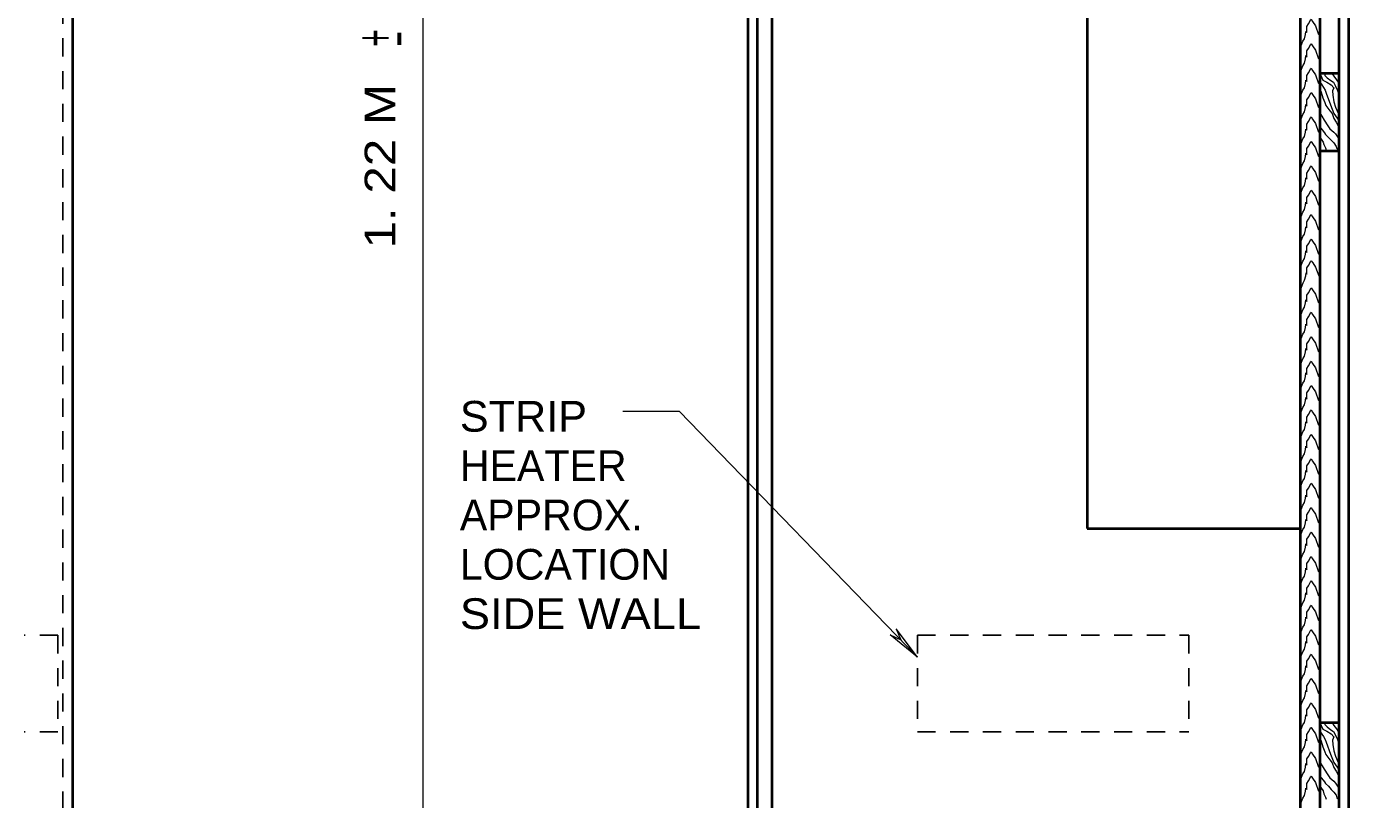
# Model space of a CAD drawing. Extents: x 312583 to 312854, y 144419 to 144597.
# Drawn here: x 312696.89 to 312729.57, y 144529.22 to 144548.34 of the extents above; entities that cross this region are included whole.
import ezdxf
from ezdxf.enums import TextEntityAlignment as Align

# ---------------------------------------------------------------- set-up
doc = ezdxf.new("R2010")
doc.units = 0
doc.header["$LTSCALE"] = 0.3
doc.linetypes.add('SHORT_DASHED', pattern=[2.7, 1.5, -1.2])
doc.layers.add('1', color=7, linetype='Continuous', lineweight=25)
doc.layers.add('2', color=7, linetype='Continuous', lineweight=13)

msp = doc.modelspace()

# ---------------------------------------------------------------- linework, layer by layer
at = {"layer": '1', "lineweight": 40}
for p, q in [((312728.3725, 144566.588), (312728.3725, 144526.338)), ((312728.8555, 144566.542), (312728.8555, 144526.3763)), ((312698.0298, 144565.8673), (312698.0298, 144527.2963)), ((312729.3309, 144565.8673), (312729.3309, 144527.0586)), ((312729.5685, 144565.8673), (312729.5685, 144527.0586)), ((312715.3162, 144564.7863), (312715.3162, 144528.73)), ((312714.9559, 144564.6253), (312714.9559, 144528.8986)), ((312723.1055, 144562.034), (312723.1055, 144535.9213)), ((312728.8555, 144547.1836), (312729.3309, 144547.1836)), ((312728.8555, 144545.267), (312729.3309, 144545.267)), ((312723.1055, 144535.9213), (312728.3725, 144535.9213)), ((312728.8555, 144531.1296), (312729.3309, 144531.1296))]:
    msp.add_line(p, q, dxfattribs=at)
at = {"layer": '1', "linetype": 'SHORT_DASHED'}
for p, q in [((312697.7921, 144565.8673), (312697.7921, 144527.2963)), ((312697.6695, 144533.284), (312696.8338, 144533.284)), ((312697.6695, 144533.284), (312697.6695, 144530.892)), ((312718.9119, 144533.284), (312725.6202, 144533.284)), ((312718.9119, 144533.284), (312718.9119, 144530.892)), ((312725.6202, 144533.284), (312725.6202, 144530.892)), ((312697.6695, 144530.892), (312696.8338, 144530.892)), ((312718.9119, 144530.892), (312725.6202, 144530.892))]:
    msp.add_line(p, q, dxfattribs=at)
at = {"layer": '1', "lineweight": 40}
msp.add_lwpolyline([(312714.7182, 144565.8673), (312714.7182, 144528.2546), (312714.7182, 144527.0586)], dxfattribs=at)
at = {"layer": '2'}
for p, q in [((312706.6978, 144520.8256), (312706.6978, 144566.8256)), ((312711.6283, 144538.8276), (312713.0219, 144538.8276)), ((312718.9119, 144532.7419), (312713.0219, 144538.8276)), ((312718.2351, 144533.2932), (312718.5035, 144533.1681)), ((312718.9119, 144532.7419), (312718.2351, 144533.2932)), ((312718.39, 144533.4416), (312718.5035, 144533.1681)), ((312718.9119, 144532.7419), (312718.39, 144533.4416))]:
    msp.add_line(p, q, dxfattribs=at)
for points in [[(312728.3879, 144547.843), (312728.4415, 144547.9733), (312728.4799, 144548.0346), (312728.5029, 144548.142), (312728.5105, 144548.2186), (312728.5335, 144548.188), (312728.5335, 144548.2723), (312728.5335, 144548.3413), (312728.5795, 144548.4026), (312728.6332, 144548.51), (312728.6409, 144548.5176), (312728.6792, 144548.464), (312728.7482, 144548.3566), (312728.8249, 144548.142)], [(312728.3879, 144547.245), (312728.4415, 144547.3676), (312728.4799, 144547.429), (312728.5029, 144547.5363), (312728.5105, 144547.6206), (312728.5335, 144547.5823), (312728.5335, 144547.6743), (312728.5335, 144547.7356), (312728.5795, 144547.797), (312728.6332, 144547.9043), (312728.6409, 144547.912), (312728.6792, 144547.8583), (312728.7482, 144547.751), (312728.8249, 144547.5363)], [(312728.3879, 144546.6393), (312728.4415, 144546.762), (312728.4799, 144546.8233), (312728.5029, 144546.9306), (312728.5105, 144547.015), (312728.5335, 144546.9766), (312728.5335, 144547.0686), (312728.5335, 144547.13), (312728.5795, 144547.1913), (312728.6332, 144547.2986), (312728.6409, 144547.3063), (312728.6792, 144547.2526), (312728.7482, 144547.1453), (312728.8249, 144546.9306)], [(312728.8555, 144547.1836), (312728.9322, 144547.015), (312729.0319, 144546.9613), (312729.1392, 144546.9), (312729.2005, 144546.8233), (312729.1699, 144546.7466), (312729.1775, 144546.6393), (312729.2005, 144546.4783), (312729.2465, 144546.348), (312729.3079, 144546.1946), (312729.3309, 144546.141)], [(312728.9782, 144547.1836), (312728.9859, 144547.13), (312729.0395, 144547.0686), (312729.1315, 144546.9996), (312729.1929, 144546.9613), (312729.2465, 144546.8616), (312729.2925, 144546.7543), (312729.3309, 144546.6623)], [(312729.1622, 144547.1683), (312729.2005, 144547.107), (312729.2695, 144547.0226), (312729.3155, 144546.9613)], [(312728.3879, 144546.0336), (312728.4415, 144546.164), (312728.4799, 144546.2253), (312728.5029, 144546.3326), (312728.5105, 144546.4093), (312728.5335, 144546.371), (312728.5335, 144546.463), (312728.5335, 144546.5243), (312728.5795, 144546.5856), (312728.6332, 144546.693), (312728.6409, 144546.7083), (312728.6792, 144546.6546), (312728.7482, 144546.5473), (312728.8249, 144546.3326)], [(312728.8632, 144546.9536), (312728.9092, 144546.8923), (312728.9475, 144546.831), (312728.9935, 144546.762), (312729.0165, 144546.693), (312729.1239, 144546.4016), (312729.2082, 144546.187), (312729.3309, 144546.0183)], [(312728.8632, 144546.7773), (312728.8939, 144546.716), (312728.9322, 144546.578), (312728.9782, 144546.4553), (312729.0089, 144546.3863), (312729.1085, 144546.256), (312729.1622, 144546.187), (312729.2082, 144546.0643), (312729.2619, 144545.9723), (312729.3232, 144545.865)], [(312728.3879, 144545.428), (312728.4415, 144545.5583), (312728.4799, 144545.6196), (312728.5029, 144545.727), (312728.5105, 144545.8036), (312728.5335, 144545.773), (312728.5335, 144545.8573), (312728.5335, 144545.9263), (312728.5795, 144545.9876), (312728.6332, 144546.095), (312728.6409, 144546.1026), (312728.6792, 144546.049), (312728.7482, 144545.9416), (312728.8249, 144545.727)], [(312728.8479, 144546.2176), (312728.9629, 144546.026), (312729.0549, 144545.8803), (312729.1085, 144545.8113), (312729.2005, 144545.727), (312729.2465, 144545.681), (312729.3309, 144545.5583)], [(312728.8555, 144545.8573), (312728.9705, 144545.7116), (312729.0012, 144545.6656), (312729.0702, 144545.5966), (312729.1392, 144545.5276), (312729.2005, 144545.4586), (312729.2619, 144545.3743), (312729.2772, 144545.3206), (312729.3232, 144545.2823)], [(312728.3879, 144544.83), (312728.4415, 144544.9526), (312728.4799, 144545.014), (312728.5029, 144545.1213), (312728.5105, 144545.2056), (312728.5335, 144545.1673), (312728.5335, 144545.2593), (312728.5335, 144545.3206), (312728.5795, 144545.382), (312728.6332, 144545.4893), (312728.6409, 144545.497), (312728.6792, 144545.4433), (312728.7482, 144545.336), (312728.8249, 144545.1213)], [(312728.8555, 144545.6043), (312728.9399, 144545.4816), (312728.9552, 144545.4203), (312729.0012, 144545.336), (312729.0165, 144545.2823)], [(312728.3879, 144544.2243), (312728.4415, 144544.347), (312728.4799, 144544.4083), (312728.5029, 144544.5156), (312728.5105, 144544.6), (312728.5335, 144544.5616), (312728.5335, 144544.6536), (312728.5335, 144544.715), (312728.5795, 144544.7763), (312728.6332, 144544.8836), (312728.6409, 144544.8913), (312728.6792, 144544.8376), (312728.7482, 144544.7303), (312728.8249, 144544.5156)], [(312728.3879, 144543.6186), (312728.4415, 144543.749), (312728.4799, 144543.8103), (312728.5029, 144543.9176), (312728.5105, 144543.9943), (312728.5335, 144543.956), (312728.5335, 144544.048), (312728.5335, 144544.1093), (312728.5795, 144544.1706), (312728.6332, 144544.278), (312728.6409, 144544.2933), (312728.6792, 144544.2396), (312728.7482, 144544.1323), (312728.8249, 144543.9176)], [(312728.3879, 144543.013), (312728.4415, 144543.1433), (312728.4799, 144543.2046), (312728.5029, 144543.312), (312728.5105, 144543.3886), (312728.5335, 144543.358), (312728.5335, 144543.4423), (312728.5335, 144543.5113), (312728.5795, 144543.5726), (312728.6332, 144543.68), (312728.6409, 144543.6876), (312728.6792, 144543.634), (312728.7482, 144543.5266), (312728.8249, 144543.312)], [(312728.3879, 144542.415), (312728.4415, 144542.5376), (312728.4799, 144542.599), (312728.5029, 144542.7063), (312728.5105, 144542.7906), (312728.5335, 144542.7523), (312728.5335, 144542.8443), (312728.5335, 144542.9056), (312728.5795, 144542.967), (312728.6332, 144543.0743), (312728.6409, 144543.082), (312728.6792, 144543.0283), (312728.7482, 144542.921), (312728.8249, 144542.7063)], [(312728.3955, 144541.8706), (312728.4492, 144542.001), (312728.4799, 144542.0623), (312728.5105, 144542.1696), (312728.5182, 144542.2463), (312728.5335, 144542.2156), (312728.5335, 144542.3), (312728.5335, 144542.369), (312728.5795, 144542.4303), (312728.6332, 144542.5376), (312728.6409, 144542.5453), (312728.6869, 144542.4916), (312728.7482, 144542.3843), (312728.8325, 144542.1696)], [(312728.3879, 144541.2036), (312728.4415, 144541.334), (312728.4799, 144541.3953), (312728.5029, 144541.5026), (312728.5105, 144541.5793), (312728.5335, 144541.541), (312728.5335, 144541.633), (312728.5335, 144541.6943), (312728.5795, 144541.7556), (312728.6332, 144541.863), (312728.6409, 144541.8783), (312728.6792, 144541.8246), (312728.7482, 144541.7173), (312728.8249, 144541.5026)], [(312728.3879, 144540.598), (312728.4415, 144540.7283), (312728.4799, 144540.7896), (312728.5029, 144540.897), (312728.5105, 144540.9736), (312728.5335, 144540.943), (312728.5335, 144541.0273), (312728.5335, 144541.0963), (312728.5795, 144541.1576), (312728.6332, 144541.265), (312728.6409, 144541.2726), (312728.6792, 144541.219), (312728.7482, 144541.1116), (312728.8249, 144540.897)], [(312728.3879, 144540), (312728.4415, 144540.1226), (312728.4799, 144540.184), (312728.5029, 144540.2913), (312728.5105, 144540.3756), (312728.5335, 144540.3373), (312728.5335, 144540.4293), (312728.5335, 144540.4906), (312728.5795, 144540.552), (312728.6332, 144540.6593), (312728.6409, 144540.667), (312728.6792, 144540.6133), (312728.7482, 144540.506), (312728.8249, 144540.2913)], [(312728.3879, 144539.3943), (312728.4415, 144539.517), (312728.4799, 144539.5783), (312728.5029, 144539.6856), (312728.5105, 144539.77), (312728.5335, 144539.7316), (312728.5335, 144539.8236), (312728.5335, 144539.885), (312728.5795, 144539.9463), (312728.6332, 144540.0536), (312728.6409, 144540.0613), (312728.6792, 144540.0076), (312728.7482, 144539.9003), (312728.8249, 144539.6856)], [(312728.3879, 144538.7886), (312728.4415, 144538.919), (312728.4799, 144538.9803), (312728.5029, 144539.0876), (312728.5105, 144539.1643), (312728.5335, 144539.126), (312728.5335, 144539.218), (312728.5335, 144539.2793), (312728.5795, 144539.3406), (312728.6332, 144539.448), (312728.6409, 144539.4633), (312728.6792, 144539.4096), (312728.7482, 144539.3023), (312728.8249, 144539.0876)], [(312728.3879, 144538.183), (312728.4415, 144538.3133), (312728.4799, 144538.3746), (312728.5029, 144538.482), (312728.5105, 144538.5586), (312728.5335, 144538.528), (312728.5335, 144538.6123), (312728.5335, 144538.6813), (312728.5795, 144538.7426), (312728.6332, 144538.85), (312728.6409, 144538.8576), (312728.6792, 144538.804), (312728.7482, 144538.6966), (312728.8249, 144538.482)], [(312728.3879, 144537.585), (312728.4415, 144537.7076), (312728.4799, 144537.769), (312728.5029, 144537.8763), (312728.5105, 144537.9606), (312728.5335, 144537.9223), (312728.5335, 144538.0143), (312728.5335, 144538.0756), (312728.5795, 144538.137), (312728.6332, 144538.2443), (312728.6409, 144538.252), (312728.6792, 144538.1983), (312728.7482, 144538.091), (312728.8249, 144537.8763)], [(312728.3879, 144536.9793), (312728.4415, 144537.102), (312728.4799, 144537.1633), (312728.5029, 144537.2706), (312728.5105, 144537.355), (312728.5335, 144537.3166), (312728.5335, 144537.4086), (312728.5335, 144537.47), (312728.5795, 144537.5313), (312728.6332, 144537.6386), (312728.6409, 144537.6463), (312728.6792, 144537.5926), (312728.7482, 144537.4853), (312728.8249, 144537.2706)], [(312728.3879, 144536.3736), (312728.4415, 144536.504), (312728.4799, 144536.5653), (312728.5029, 144536.6726), (312728.5105, 144536.7493), (312728.5335, 144536.711), (312728.5335, 144536.803), (312728.5335, 144536.8643), (312728.5795, 144536.9256), (312728.6332, 144537.033), (312728.6409, 144537.0483), (312728.6792, 144536.9946), (312728.7482, 144536.8873), (312728.8249, 144536.6726)], [(312728.3879, 144535.768), (312728.4415, 144535.8983), (312728.4799, 144535.9596), (312728.5029, 144536.067), (312728.5105, 144536.1436), (312728.5335, 144536.113), (312728.5335, 144536.1973), (312728.5335, 144536.2663), (312728.5795, 144536.3276), (312728.6332, 144536.435), (312728.6409, 144536.4426), (312728.6792, 144536.389), (312728.7482, 144536.2816), (312728.8249, 144536.067)], [(312728.3879, 144535.17), (312728.4415, 144535.2926), (312728.4799, 144535.354), (312728.5029, 144535.4613), (312728.5105, 144535.5456), (312728.5335, 144535.5073), (312728.5335, 144535.5993), (312728.5335, 144535.6606), (312728.5795, 144535.722), (312728.6332, 144535.8293), (312728.6409, 144535.837), (312728.6792, 144535.7833), (312728.7482, 144535.676), (312728.8249, 144535.4613)], [(312728.3879, 144534.5643), (312728.4415, 144534.687), (312728.4799, 144534.7483), (312728.5029, 144534.8556), (312728.5105, 144534.94), (312728.5335, 144534.9016), (312728.5335, 144534.9936), (312728.5335, 144535.055), (312728.5795, 144535.1163), (312728.6332, 144535.2236), (312728.6409, 144535.2313), (312728.6792, 144535.1776), (312728.7482, 144535.0703), (312728.8249, 144534.8556)], [(312728.3879, 144533.9586), (312728.4415, 144534.089), (312728.4799, 144534.1503), (312728.5029, 144534.2576), (312728.5105, 144534.3343), (312728.5335, 144534.296), (312728.5335, 144534.388), (312728.5335, 144534.4493), (312728.5795, 144534.5106), (312728.6332, 144534.618), (312728.6409, 144534.6333), (312728.6792, 144534.5796), (312728.7482, 144534.4723), (312728.8249, 144534.2576)], [(312728.3879, 144533.353), (312728.4415, 144533.4833), (312728.4799, 144533.5446), (312728.5029, 144533.652), (312728.5105, 144533.7286), (312728.5335, 144533.698), (312728.5335, 144533.7823), (312728.5335, 144533.8513), (312728.5795, 144533.9126), (312728.6332, 144534.02), (312728.6409, 144534.0276), (312728.6792, 144533.974), (312728.7482, 144533.8666), (312728.8249, 144533.652)], [(312728.3879, 144532.755), (312728.4415, 144532.8776), (312728.4799, 144532.939), (312728.5029, 144533.0463), (312728.5105, 144533.1306), (312728.5335, 144533.0923), (312728.5335, 144533.1843), (312728.5335, 144533.2456), (312728.5795, 144533.307), (312728.6332, 144533.4143), (312728.6409, 144533.422), (312728.6792, 144533.3683), (312728.7482, 144533.261), (312728.8249, 144533.0463)], [(312728.3879, 144532.1493), (312728.4415, 144532.272), (312728.4799, 144532.3333), (312728.5029, 144532.4406), (312728.5105, 144532.525), (312728.5335, 144532.4866), (312728.5335, 144532.5786), (312728.5335, 144532.64), (312728.5795, 144532.7013), (312728.6332, 144532.8086), (312728.6409, 144532.8163), (312728.6792, 144532.7626), (312728.7482, 144532.6553), (312728.8249, 144532.4406)], [(312728.3879, 144531.5436), (312728.4415, 144531.674), (312728.4799, 144531.7353), (312728.5029, 144531.8426), (312728.5105, 144531.9193), (312728.5335, 144531.881), (312728.5335, 144531.973), (312728.5335, 144532.0343), (312728.5795, 144532.0956), (312728.6332, 144532.203), (312728.6409, 144532.2183), (312728.6792, 144532.1646), (312728.7482, 144532.0573), (312728.8249, 144531.8426)], [(312728.3879, 144530.938), (312728.4415, 144531.0683), (312728.4799, 144531.1296), (312728.5029, 144531.237), (312728.5105, 144531.3136), (312728.5335, 144531.283), (312728.5335, 144531.3673), (312728.5335, 144531.4363), (312728.5795, 144531.4976), (312728.6332, 144531.605), (312728.6409, 144531.6126), (312728.6792, 144531.559), (312728.7482, 144531.4516), (312728.8249, 144531.237)], [(312728.3879, 144530.34), (312728.4415, 144530.4626), (312728.4799, 144530.524), (312728.5029, 144530.6313), (312728.5105, 144530.7156), (312728.5335, 144530.6773), (312728.5335, 144530.7693), (312728.5335, 144530.8306), (312728.5795, 144530.892), (312728.6332, 144530.9993), (312728.6409, 144531.007), (312728.6792, 144530.9533), (312728.7482, 144530.846), (312728.8249, 144530.6313)], [(312728.8555, 144531.1296), (312728.9322, 144530.961), (312729.0319, 144530.915), (312729.1392, 144530.846), (312729.2005, 144530.7693), (312729.1699, 144530.6926), (312729.1775, 144530.5853), (312729.2005, 144530.4243), (312729.2465, 144530.294), (312729.3079, 144530.1406), (312729.3309, 144530.087)], [(312728.9782, 144531.1296), (312728.9859, 144531.076), (312729.0395, 144531.0223), (312729.1315, 144530.9456), (312729.1929, 144530.9073), (312729.2465, 144530.8153), (312729.2925, 144530.708), (312729.3309, 144530.616)], [(312729.1622, 144531.122), (312729.2005, 144531.053), (312729.2695, 144530.9686), (312729.3155, 144530.9073)], [(312728.8632, 144530.9073), (312728.9092, 144530.8383), (312728.9475, 144530.777), (312728.9935, 144530.708), (312729.0165, 144530.639), (312729.1239, 144530.3476), (312729.2082, 144530.1406), (312729.3309, 144529.9643)], [(312728.8632, 144530.7233), (312728.8939, 144530.662), (312728.9322, 144530.524), (312728.9782, 144530.4013), (312729.0089, 144530.3323), (312729.1085, 144530.202), (312729.1622, 144530.133), (312729.2082, 144530.0103), (312729.2619, 144529.926), (312729.3232, 144529.8186)], [(312728.3879, 144529.7343), (312728.4415, 144529.857), (312728.4799, 144529.9183), (312728.5029, 144530.0256), (312728.5105, 144530.11), (312728.5335, 144530.0716), (312728.5335, 144530.1636), (312728.5335, 144530.225), (312728.5795, 144530.2863), (312728.6332, 144530.3936), (312728.6409, 144530.4013), (312728.6792, 144530.3476), (312728.7482, 144530.2403), (312728.8249, 144530.0256)], [(312728.8479, 144530.1636), (312728.9629, 144529.972), (312729.0549, 144529.834), (312729.1085, 144529.7573), (312729.2005, 144529.673), (312729.2465, 144529.627), (312729.3309, 144529.5043)], [(312728.3879, 144529.1286), (312728.4415, 144529.259), (312728.4799, 144529.3203), (312728.5029, 144529.4276), (312728.5105, 144529.5043), (312728.5335, 144529.466), (312728.5335, 144529.558), (312728.5335, 144529.6193), (312728.5795, 144529.6806), (312728.6332, 144529.788), (312728.6409, 144529.8033), (312728.6792, 144529.7496), (312728.7482, 144529.6423), (312728.8249, 144529.4276)], [(312728.8555, 144529.8033), (312728.9705, 144529.6576), (312729.0012, 144529.6193), (312729.0702, 144529.5503), (312729.1392, 144529.4736), (312729.2005, 144529.4046), (312729.2619, 144529.328), (312729.2772, 144529.2666), (312729.3232, 144529.2283)], [(312728.8555, 144529.5503), (312728.9399, 144529.4353), (312728.9552, 144529.3663), (312729.0012, 144529.282), (312729.0165, 144529.2283)]]:
    msp.add_lwpolyline(points, dxfattribs=at)

# ---------------------------------------------------------------- texts
at = {"layer": '2', "width": 0.6}
msp.add_text('+', height=0.92, rotation=90, dxfattribs=at).set_placement((312705.9622, 144548.0537), align=Align.CENTER)
at = {"layer": '2'}
msp.add_text('-', height=0.92, rotation=90, dxfattribs=at).set_placement((312706.4627, 144548.0347), align=Align.CENTER)
at = {"layer": '2', "width": 1.2}
msp.add_text('1. 22 M', height=0.76, rotation=90, dxfattribs=at).set_placement((312706.0115, 144542.8492))
at = {"layer": '2'}
for s, width, p in [('STRIP', 1.05, (312707.6032, 144538.3189)), ('SIDE WALL', 1.1, (312707.6032, 144533.4389))]:
    msp.add_text(s, height=0.76, dxfattribs=dict(at, width=width)).set_placement(p)
for s, p in [('HEATER', (312707.6032, 144537.0989)), ('APPROX.', (312707.6032, 144535.8789)), ('LOCATION', (312707.6032, 144534.6589))]:
    msp.add_text(s, height=0.76, dxfattribs=at).set_placement(p)

doc.saveas('drawing.dxf')
